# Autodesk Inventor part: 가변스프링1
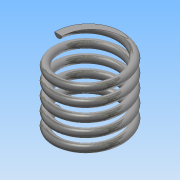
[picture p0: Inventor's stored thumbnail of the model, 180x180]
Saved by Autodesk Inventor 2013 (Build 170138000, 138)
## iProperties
Created: 2016-03
Part Number: 가변스프링1
Material: 스테인리스강
Document SubType Name: Modeling
Designer: Administrator
Density: 8.08 g/cm^3
Mass: 6.61408 g
Surface Area: 16.6837 cm^2
Volume: 0.818574 cm^3
Author: Administrator
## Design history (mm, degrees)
sketch "스케치1"
  geometry: L1 (0, 0)-(8.5, 0); L2 (8.5, 17.5)-(0, 17.5); L3 (0, 17.5)-(0, 0); C1 r 1 at (8.5, 0)
  constraints: 6 end point, 2 parallel, 1 centre point, 1 coincident, 1 horizontal, 1 vertical
  dimensions: "d0" = 2 diameter of C1; "d1" = 17 diameter of C1.centre L3; "d2" = 17.5 distance between parallel lines of L1 L2 (derived)
feature "코일1" sketch "스케치1" pitch "d3" = 10; turns "d5" = 5; dims "d4" = 17.5 (= d2), "d6" = 0, angle "d7" = 90 deg, angle "d8" = 90 deg, "d9" = 0, "d10" = 0
sketch "스케치2"
  geometry: L1 (-10, 17.5)-(10, 17.5); L2 (10, 17.5)-(10, 0); L3 (10, 0)-(-10, 0); L4 (-10, 0)-(-10, 17.5); 2 further points
  constraints: 8 end point, 2 parallel, 1 coincident, 1 horizontal, 1 midpoint, 1 perpendicular
  dimensions: "d11" = 17.5 distance between parallel lines of L3 L1 (derived); "d13" = 20 distance of L1.start L1.end
extrude "돌출1" sketch "스케치2" stored distance "d14" = 10; taper "d15" = 0 deg
node "솔리드1"
